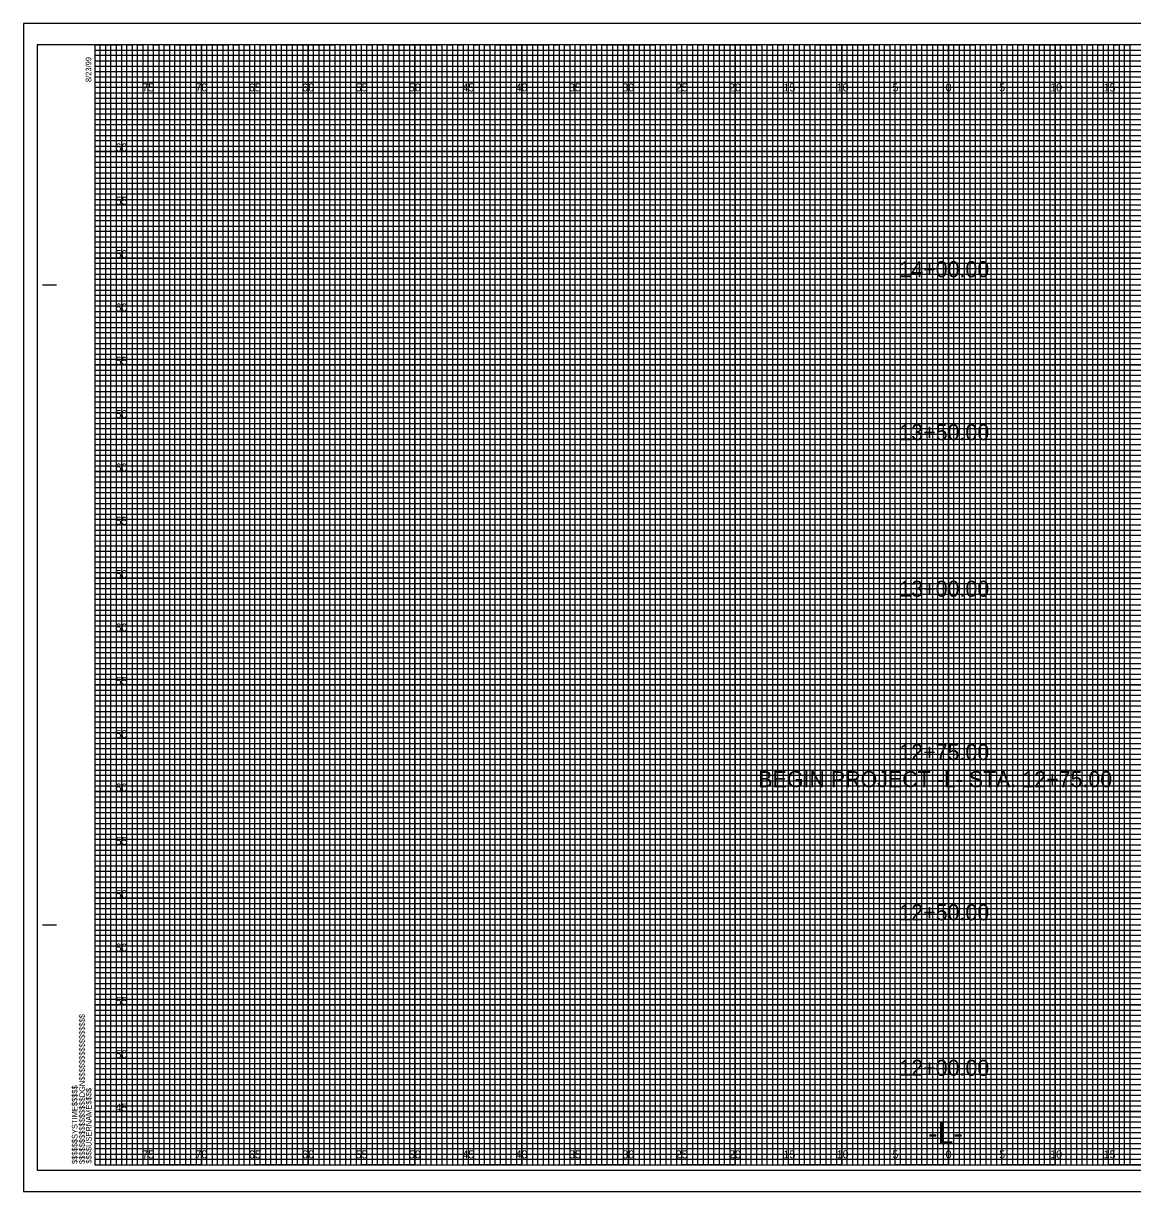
# Model space of a CAD drawing. Extents: x -7 to 193, y -2 to 107.
# Drawn here: x -6.7 to 97.2, y -2.5 to 107 of the extents above; entities that cross this region are included whole.
import ezdxf

# ---------------------------------------------------------------- set-up
doc = ezdxf.new("R2010")
doc.units = 0
for name, color, linetype in [('Exist XS Center Line Elevation Label', 7, 'Continuous'), ('Prop XS Alignment Label', 7, 'Continuous'), ('Prop XS Elevation Labels', 7, 'Continuous'), ('Prop XS Offset Labels', 7, 'Continuous'), ('Prop XS Station Labels', 7, 'Continuous'), ('Sheet Cross Section CELL', 7, 'Continuous'), ('Sheet Cross Section Grid Major CELL', 7, 'Continuous'), ('Sheet Cross Section Grid Middle CELL', 7, 'Continuous'), ('Sheet Cross Section Grid Minor 1 CELL', 7, 'Continuous'), ('Sheet Cross Section Grid Minor 2 CELL', 7, 'Continuous'), ('Sheet Cutting Line CELL', 7, 'Continuous'), ('Sheet DOT Grid CELL', 7, 'Continuous'), ('Sheet Plot Border Inside CELL', 7, 'Continuous'), ('Sheet Plot Border Outside CELL', 7, 'Continuous')]:
    doc.layers.add(name, color=color, linetype=linetype)

msp = doc.modelspace()

# ---------------------------------------------------------------- linework, layer by layer
at = {"layer": 'Sheet Cross Section CELL'}
for p, q in [((-4.9, 82.5), (-3.65, 82.5)), ((-4.85, 82.5), (-3.6, 82.5)), ((-4.9, 22.5), (-3.65, 22.5)), ((-4.85, 22.5), (-3.6, 22.5)), ((0, 0), (0, 0)), ((0, 0), (0, 0)), ((0, 0), (0, 0)), ((0, 0), (0, 0)), ((0, 0), (0, 0)), ((0, 0), (0, 0)), ((0, 0), (0, 0))]:
    msp.add_line(p, q, dxfattribs=at)
msp.add_lwpolyline([(160, 105), (0, 105), (0, 0), (160, 0)], close=True, dxfattribs=at)
at = {"layer": 'Sheet Cross Section Grid Major CELL'}
for p, q in [((5, 105), (0, 105)), ((5, 0), (5, 105)), ((15, 105), (10, 105)), ((10, 105), (10, 0)), ((15, 0), (15, 105)), ((25, 105), (20, 105)), ((20, 105), (20, 0)), ((25, 0), (25, 105)), ((35, 105), (30, 105)), ((30, 105), (30, 0)), ((35, 0), (35, 105)), ((45, 105), (40, 105)), ((40, 105), (40, 0)), ((45, 0), (45, 105)), ((55, 105), (50, 105)), ((50, 105), (50, 0)), ((55, 0), (55, 105)), ((65, 105), (60, 105)), ((60, 105), (60, 0)), ((65, 0), (65, 105)), ((75, 105), (70, 105)), ((70, 105), (70, 0)), ((75, 0), (75, 105)), ((85, 105), (80, 105)), ((80, 105), (80, 0)), ((85, 0), (85, 105)), ((95, 105), (90, 105)), ((90, 105), (90, 0)), ((95, 0), (95, 105)), ((10, 0), (5, 0)), ((20, 0), (15, 0)), ((30, 0), (25, 0)), ((40, 0), (35, 0)), ((50, 0), (45, 0)), ((60, 0), (55, 0)), ((70, 0), (65, 0)), ((80, 0), (75, 0)), ((90, 0), (85, 0)), ((100, 0), (95, 0))]:
    msp.add_line(p, q, dxfattribs=at)
for points in [[(0, 100), (160, 100), (160, 95), (0, 95)], [(0, 90), (160, 90), (160, 85), (0, 85)], [(0, 80), (160, 80), (160, 75), (0, 75)], [(0, 70), (160, 70), (160, 65), (0, 65)], [(0, 60), (160, 60), (160, 55), (0, 55)], [(0, 50), (160, 50), (160, 45), (0, 45)], [(0, 40), (160, 40), (160, 35), (0, 35)], [(0, 30), (160, 30), (160, 25), (0, 25)], [(0, 20), (160, 20), (160, 15), (0, 15)], [(0, 10), (160, 10), (160, 5), (0, 5)]]:
    msp.add_lwpolyline(points, dxfattribs=at)
at = {"layer": 'Sheet Cross Section Grid Middle CELL'}
for points in [[(0, 105), (2.5, 105), (2.5, 0), (7.5, 0), (7.5, 105), (12.5, 105), (12.5, 0), (17.5, 0), (17.5, 105), (22.5, 105), (22.5, 0), (27.5, 0), (27.5, 105), (32.5, 105), (32.5, 0), (37.5, 0), (37.5, 105), (42.5, 105), (42.5, 0), (47.5, 0), (47.5, 105), (52.5, 105), (52.5, 0), (57.5, 0), (57.5, 105), (62.5, 105), (62.5, 0), (67.5, 0), (67.5, 105), (72.5, 105), (72.5, 0), (77.5, 0), (77.5, 105), (82.5, 105), (82.5, 0), (87.5, 0), (87.5, 105), (92.5, 105), (92.5, 0), (97.5, 0)], [(0, 102.5), (137.5, 102.5)], [(135, 92.5), (160, 92.5), (160, 97.5), (0, 97.5)], [(0, 92.5), (130, 92.5)], [(0, 82.5), (160, 82.5), (160, 87.5), (0, 87.5)], [(0, 72.5), (160, 72.5), (160, 77.5), (0, 77.5)], [(0, 62.5), (160, 62.5), (160, 67.5), (0, 67.5)], [(0, 52.5), (160, 52.5), (160, 57.5), (0, 57.5)], [(0, 42.5), (160, 42.5), (160, 47.5), (0, 47.5)], [(0, 32.5), (160, 32.5), (160, 37.5), (0, 37.5)], [(0, 22.5), (160, 22.5), (160, 27.5), (0, 27.5)], [(0, 12.5), (160, 12.5), (160, 17.5), (0, 17.5)], [(0, 2.5), (160, 2.5), (160, 7.5), (0, 7.5)]]:
    msp.add_lwpolyline(points, dxfattribs=at)
at = {"layer": 'Sheet Cross Section Grid Minor 1 CELL'}
for p, q in [((0, 104.5), (130, 104.5)), ((130, 103.99), (0, 103.99)), ((0, 103.99), (0, 103.5)), ((0, 103.5), (130, 103.5)), ((130, 102.95), (0, 102.95)), ((0, 102.95), (0, 102)), ((0, 102), (160, 102))]:
    msp.add_line(p, q, dxfattribs=at)
for points in [[(0, 101.5), (135, 101.5), (160, 101.5), (160, 101), (0, 101)], [(0, 100.5), (160, 100.5), (160, 99.5), (0, 99.5)], [(0, 99), (160, 99), (160, 98.5), (0, 98.49)], [(0, 98), (160, 98), (160, 97), (0, 97)], [(0, 96.5), (160, 96.5), (160, 96), (0, 96)], [(0, 95.5), (160, 95.5), (160, 94.5), (135, 94.5)], [(130, 94.5), (0, 94.5)], [(0, 94), (130, 94)], [(130, 93.5), (0, 93.5)], [(0, 93), (130, 93)], [(130, 92), (0, 92)], [(0, 91.5), (160, 91.5), (160, 91), (0, 91)], [(0, 90.5), (160, 90.5), (160, 89.5), (0, 89.5)], [(0, 89), (160, 89), (160, 88.5), (0, 88.5)], [(0, 88), (160, 88), (160, 86.98), (160, 86.5), (160, 86), (0, 86)], [(0, 87), (160, 87), (160, 86.5), (0, 86.5)], [(0, 85.5), (160, 85.5), (160, 84.5), (0, 84.52)], [(0, 84.52), (160, 84.5), (160, 84), (0, 84)], [(0, 83.5), (160, 83.5), (160, 83), (0, 83)], [(0, 82), (160, 82), (160, 81.5), (0, 81.5)], [(0, 81), (160, 81), (160, 80.5), (0, 80.5)], [(-0.04, 79.45), (160, 79.45), (160, 78.94), (-0.04, 78.94)], [(0, 78.5), (160, 78.5), (160, 78), (0, 78)], [(0, 77), (160, 77), (160, 76.5), (0, 76.5)], [(0, 76), (160, 76), (160, 75.5), (0, 75.5)], [(0, 74.5), (160, 74.5), (160, 74), (0, 74)], [(0, 73.5), (160, 73.5), (160, 73), (0, 73)], [(0, 72), (160, 72), (160, 71.5), (0, 71.5)], [(0, 71), (160, 71), (160, 70.5), (0, 70.5)], [(0, 69.5), (160, 69.5), (160, 68.99), (0, 69)], [(0, 68.5), (160, 68.5), (160, 68), (0, 68)], [(0, 67), (160, 67), (160, 66.5), (0, 66.5)], [(0, 66), (160, 66), (160, 65.5), (0, 65.5)], [(0, 64.5), (160, 64.5), (160, 64), (0, 64)], [(0, 63.5), (160, 63.5), (160, 63), (0, 63)], [(0, 62), (160, 62), (160, 61.5), (0, 61.5)], [(0, 61), (160, 61), (160, 60.5), (0, 60.5)], [(0, 59.5), (160, 59.5), (160, 59), (0, 59)], [(0, 58.5), (160.03, 58.45), (160, 58), (0, 58)], [(0, 57), (160, 57), (160, 56.5), (0, 56.5)], [(0, 56), (160, 56), (160, 55.5), (0, 55.5)], [(0, 54.5), (160, 54.5), (160, 54), (0, 54)], [(0, 53.5), (160, 53.5), (160, 53), (0, 53)], [(0, 52), (160, 52), (160, 51.5), (0, 51.5)], [(0, 51), (160, 51), (160, 50.5), (0, 50.5)], [(0, 49.5), (160, 49.5), (160, 49), (0, 49)], [(0, 48.5), (160, 48.5), (160, 48), (0, 48)], [(0, 47), (160, 47), (160, 46.5), (0, 46.5)], [(0, 46), (160, 46), (160, 45.5), (0, 45.5)], [(0, 44.5), (160, 44.5), (160, 44), (0, 44)], [(0, 43.5), (160, 43.5), (160, 43), (0, 43)], [(0, 42), (160, 42), (160, 41.5), (0, 41.5)], [(0, 41), (160, 41), (160, 40.5), (0, 40.5)], [(0, 39.5), (160, 39.5), (160, 38.99), (0, 39)], [(0, 38.5), (160, 38.5), (160, 38), (0, 38)], [(0, 37), (160, 37), (160, 36.5), (0, 36.5)], [(0, 36), (160, 36), (160, 35.5), (0, 35.5)], [(0, 34.5), (160, 34.5), (160, 34), (0, 34)], [(0, 33.5), (160, 33.5), (160, 33), (0, 33)], [(0, 32), (160, 32), (160, 31.5), (0, 31.5)], [(0, 31), (160, 31), (160, 30.5), (0, 30.5)], [(0, 29.5), (160, 29.5), (160, 29), (0, 29)], [(0, 28.5), (160.03, 28.46), (160, 28), (0, 28)], [(0, 27), (160, 27), (160, 26.5), (0, 26.5)], [(0, 26), (160, 26), (160, 25.5), (0, 25.5)], [(0, 24.5), (160, 24.5), (160, 24), (0, 24)], [(0, 23.5), (160, 23.5), (160, 23), (0, 23)], [(0, 22), (160, 22), (160, 21.5), (0, 21.5)], [(0, 21), (160, 21), (160, 20.5), (0, 20.5)], [(0, 19.5), (160, 19.5), (160, 19), (0, 19)], [(0, 18.5), (160, 18.5), (160, 18), (0, 18)], [(0, 17), (160, 17), (160, 16.5), (0, 16.5)], [(0, 16), (160, 16), (160, 15.5), (0, 15.5)], [(0, 14.5), (160, 14.5), (160, 14), (0, 14)], [(0, 13.5), (160, 13.5), (160, 13), (0, 13)], [(0, 12), (160, 12), (160, 11.5), (0, 11.5)], [(0, 11), (160, 11), (160, 10.5), (0, 10.5)], [(0, 9.5), (160, 9.5), (160, 9), (0, 9)], [(0, 8.5), (160, 8.5), (160, 8), (0, 8)], [(0, 7), (160, 7), (160, 6.5), (0, 6.5)], [(0, 6), (160, 6), (160, 5.5), (0, 5.5)], [(0, 4.5), (160, 4.5), (160, 4), (0, 4)], [(0, 3.5), (160, 3.5), (160, 3), (0, 3)], [(0, 2), (160, 2), (160, 1.5), (0, 1.5)], [(0, 1), (160, 1), (160, 0.5), (0, 0.5)]]:
    msp.add_lwpolyline(points, dxfattribs=at)
at = {"layer": 'Sheet Cross Section Grid Minor 2 CELL'}
for points in [[(0, 0), (0.5, 0), (0.5, 105), (1, 105), (1, 0)], [(1, 0), (1.5, 0), (1.5, 105), (2, 105), (2, 0)], [(2.5, 0), (3, 0), (3, 105), (3.5, 105), (3.5, 0)], [(3.5, 0), (4, 0), (4, 105), (4.5, 105), (4.5, 0)], [(5, 0), (5.5, 0), (5.5, 105), (6, 105), (6, 0)], [(6, 0), (6.5, 0), (6.5, 105), (7, 105), (7, 0)], [(7.5, 0), (8, 0), (8, 105), (8.5, 105), (8.5, 0)], [(8.5, 0), (9, 0), (9, 105), (9.5, 105), (9.5, 0)], [(10, 0), (10.5, 0), (10.5, 105), (11, 105), (11, 0)], [(11, 0), (11.5, 0), (11.5, 105), (12, 105), (12, 0)], [(12.5, 0), (13, 0), (13, 105), (13.5, 105), (13.5, 0)], [(13.5, 0), (14, 0), (14, 105), (14.5, 105), (14.5, 0)], [(15, 0), (15.5, 0), (15.5, 105), (16, 105), (16, 0)], [(16, 0), (16.5, 0), (16.5, 105), (17, 105), (17, 0)], [(17.5, 0), (18, 0), (18, 105), (18.5, 105), (18.5, 0)], [(18.5, 0), (19, 0), (19, 105), (19.5, 105), (19.5, 0)], [(20, 0), (20.5, 0), (20.5, 105), (21, 105), (21, 0)], [(21, 0), (21.5, 0), (21.5, 105), (22, 105), (22, 0)], [(22.5, 0), (23, 0), (23, 105), (23.5, 105), (23.5, 0)], [(23.5, 0), (24, 0), (24, 105), (24.5, 105), (24.5, 0)], [(25, 0), (25.5, 0), (25.5, 105), (26, 105), (26, 0)], [(26, 0), (26.5, 0), (26.5, 105), (27, 105), (27, 0)], [(27.5, 0), (28, 0), (28, 105), (28.5, 105), (28.5, 0)], [(28.5, 0), (29, 0), (29, 105), (29.5, 105), (29.5, 0)], [(30, 0), (30.5, 0), (30.5, 105), (31, 105), (31, 0)], [(31, 0), (31.5, 0), (31.5, 105), (32, 105), (32, 0)], [(32.5, 0), (33, 0), (33, 105), (33.5, 105), (33.5, 0)], [(33.5, 0), (34, 0), (34, 105), (34.5, 105), (34.5, 0)], [(35, 0), (35.5, 0), (35.5, 105), (36, 105), (36, 0)], [(36, 0), (36.5, 0), (36.5, 105), (37, 105), (37, 0)], [(37.5, 0), (38, 0), (38, 105), (38.5, 105), (38.5, 0)], [(38.5, 0), (39, 0), (39, 105), (39.5, 105), (39.5, 0)], [(40, 0), (40.5, 0), (40.5, 105), (41, 105), (41, 0)], [(41, 0), (41.5, 0), (41.5, 105), (42, 105), (42, 0)], [(42.5, 0), (43, 0), (43, 105), (43.5, 105), (43.5, 0)], [(43.5, 0), (44, 0), (44, 105), (44.5, 105), (44.5, 0)], [(45, 0), (45.5, 0), (45.5, 105), (46, 105), (46, 0)], [(46, 0), (46.5, 0), (46.5, 105), (47, 105), (47, 0)], [(47.5, 0), (48, 0), (48, 105), (48.5, 105), (48.5, 0)], [(48.5, 0), (49, 0), (49, 105), (49.5, 105), (49.5, 0)], [(50, 0), (50.5, 0), (50.5, 105), (51, 105), (51, 0)], [(51, 0), (51.5, 0), (51.5, 105), (52, 105), (52, 0)], [(52.5, 0), (53, 0), (53, 105), (53.5, 105), (53.5, 0)], [(53.5, 0), (54, 0), (54, 105), (54.5, 105), (54.5, 0)], [(55, 0), (55.5, 0), (55.5, 105), (56, 105), (56, 0)], [(56, 0), (56.5, 0), (56.5, 105), (57, 105), (57, 0)], [(57.5, 0), (58, 0), (58, 105), (58.5, 105), (58.5, 0)], [(58.5, 0), (59, 0), (59, 105), (59.5, 105), (59.5, 0)], [(60, 0), (60.5, 0), (60.5, 105), (61, 105), (61, 0)], [(61, 0), (61.5, 0), (61.5, 105), (62, 105), (62, 0)], [(62.5, 0), (63, 0), (63, 105), (63.5, 105), (63.5, 0)], [(63.5, 0), (64, 0), (64, 105), (64.5, 105), (64.5, 0)], [(65, 0), (65.5, 0), (65.5, 105), (66, 105), (66, 0)], [(66, 0), (66.5, 0), (66.5, 105), (67, 105), (67, 0)], [(67.5, 0), (68, 0), (68, 105), (68.5, 105), (68.5, 0)], [(68.5, 0), (69, 0), (69, 105), (69.5, 105), (69.5, 0)], [(70, 0), (70.5, 0), (70.5, 105), (71, 105), (71, 0)], [(71, 0), (71.5, 0), (71.5, 105), (72, 105), (72, 0)], [(72.5, 0), (73, 0), (73, 105), (73.5, 105), (73.5, 0)], [(73.5, 0), (74, 0), (74, 105), (74.5, 105), (74.5, 0)], [(75, 0), (75.5, 0), (75.5, 105), (76, 105), (76, 0)], [(76, 0), (76.5, 0), (76.5, 105), (77, 105), (77, 0)], [(77.5, 0), (78, 0), (78, 105), (78.5, 105), (78.5, 0)], [(78.5, 0), (79, 0), (79, 105), (79.5, 105), (79.5, 0)], [(80, 0), (80.5, 0), (80.5, 105), (81, 105), (81, 0)], [(81, 0), (81.5, 0), (81.5, 105), (82, 105), (82, 0)], [(82.5, 0), (83, 0), (83, 105), (83.5, 105), (83.5, 0)], [(83.5, 0), (84, 0), (84, 105), (84.5, 105), (84.5, 0)], [(85, 0), (85.5, 0), (85.5, 105), (86, 105), (86, 0)], [(86, 0), (86.5, 0), (86.5, 105), (87, 105), (87, 0)], [(87.5, 0), (88, 0), (88, 105), (88.5, 105), (88.5, 0)], [(88.5, 0), (89, 0), (89, 105), (89.5, 105), (89.5, 0)], [(90, 0), (90.5, 0), (90.5, 105), (91, 105), (91, 0)], [(91, 0), (91.5, 0), (91.5, 105), (92, 105), (92, 0)], [(92.5, 0), (93, 0), (93, 105), (93.5, 105), (93.5, 0)], [(93.5, 0), (94, 0), (94, 105), (94.5, 105), (94.5, 0)], [(95, 0), (95.5, 0), (95.5, 105), (96, 105), (96, 0)], [(96, 0), (96.5, 0), (96.5, 105), (97, 105), (97, 0)]]:
    msp.add_lwpolyline(points, dxfattribs=at)
at = {"layer": 'Sheet Cutting Line CELL'}
for p, q in [((161.65, 107), (-6.7, 107)), ((-6.7, 107), (-6.7, -2.5)), ((-6.7, -2.5), (161.65, -2.5))]:
    msp.add_line(p, q, dxfattribs=at)
at = {"layer": 'Sheet DOT Grid CELL'}
for p, q in [((5, 0), (5, 105)), ((10, 0), (10, 105)), ((15, 0), (15, 105)), ((20, 0), (20, 105)), ((25, 0), (25, 105)), ((30, 0), (30, 105)), ((35, 0), (35, 105)), ((40, 0), (40, 105)), ((45, 0), (45, 105)), ((50, 0), (50, 105)), ((55, 0), (55, 105)), ((60, 0), (60, 105)), ((65, 0), (65, 105)), ((70, 0), (70, 105)), ((75, 0), (75, 105)), ((80, 0), (80, 105)), ((85, 0), (85, 105)), ((90, 0), (90, 105)), ((95, 0), (95, 105)), ((0, 100), (160, 100)), ((0, 95), (160, 95)), ((0, 90), (160, 90)), ((0, 85), (160, 85)), ((0, 80), (160, 80)), ((0, 75), (160, 75)), ((0, 70), (160, 70)), ((0, 65), (160, 65)), ((0, 60), (160, 60)), ((0, 55), (160, 55)), ((0, 50), (160, 50)), ((0, 45), (160, 45)), ((0, 40), (160, 40)), ((0, 35), (160, 35)), ((0, 30), (160, 30)), ((0, 25), (160, 25)), ((0, 20), (160, 20)), ((0, 15), (160, 15)), ((0, 10), (160, 10)), ((0, 5), (160, 5))]:
    msp.add_line(p, q, dxfattribs=at)
at = {"layer": 'Sheet Plot Border Inside CELL'}
msp.add_lwpolyline([(-5.4, -0.5), (161.2, -0.5), (161.2, 105), (-5.4, 105)], close=True, dxfattribs=at)
at = {"layer": 'Sheet Plot Border Outside CELL'}
msp.add_lwpolyline([(-6.7, -2.5), (161.65, -2.5), (161.65, 107), (-6.7, 107)], close=True, dxfattribs=at)

# ---------------------------------------------------------------- texts
at = {"layer": 'Exist XS Center Line Elevation Label'}
msp.add_text('BEGIN PROJECT -L- STA. 12+75.00', height=1.5, dxfattribs=at).set_placement((62.17, 35.41))
at = {"layer": 'Prop XS Alignment Label'}
msp.add_text('-L-', height=2, dxfattribs=at).set_placement((78.08, 2))
at = {"layer": 'Prop XS Elevation Labels'}
for s, p in [('60', (1.93, 95)), ('55', (1.94, 90)), ('50', (1.93, 85)), ('60', (1.93, 80)), ('55', (1.94, 75)), ('50', (1.93, 70)), ('60', (1.93, 65)), ('55', (1.94, 60)), ('50', (1.93, 55)), ('60', (1.93, 50)), ('55', (1.94, 45)), ('50', (1.93, 40)), ('60', (1.93, 35)), ('55', (1.94, 30)), ('50', (1.93, 25)), ('60', (1.93, 20)), ('55', (1.94, 15)), ('50', (1.93, 10)), ('45', (1.94, 5))]:
    msp.add_text(s, height=0.75, dxfattribs=at).set_placement(p)
at = {"layer": 'Prop XS Offset Labels'}
for s, p in [('75', (4.44, 100.62)), ('70', (9.43, 100.62)), ('65', (14.44, 100.62)), ('60', (19.43, 100.62)), ('55', (24.44, 100.62)), ('50', (29.43, 100.62)), ('45', (34.44, 100.62)), ('40', (39.43, 100.62)), ('35', (44.44, 100.62)), ('30', (49.43, 100.62)), ('25', (54.44, 100.62)), ('20', (59.43, 100.62)), ('15', (64.53, 100.62)), ('10', (69.52, 100.62)), ('5', (74.74, 100.62)), ('0', (79.73, 100.62)), ('0', (79.73, 100.62)), ('5', (84.74, 100.62)), ('10', (89.52, 100.62)), ('15', (94.53, 100.62)), ('75', (4.44, 0.62)), ('70', (9.43, 0.62)), ('65', (14.44, 0.62)), ('60', (19.43, 0.62)), ('55', (24.44, 0.62)), ('50', (29.43, 0.62)), ('45', (34.44, 0.62)), ('40', (39.43, 0.62)), ('35', (44.44, 0.62)), ('30', (49.43, 0.62)), ('25', (54.44, 0.62)), ('20', (59.43, 0.62)), ('15', (64.53, 0.62)), ('10', (69.52, 0.62)), ('5', (74.74, 0.62)), ('0', (79.73, 0.62)), ('0', (79.73, 0.62)), ('5', (84.74, 0.62)), ('10', (89.52, 0.62)), ('15', (94.53, 0.62))]:
    msp.add_text(s, height=0.75, dxfattribs=at).set_placement(p)
at = {"layer": 'Prop XS Station Labels'}
for s, p in [('14+00.00', (75.39, 83.21)), ('13+50.00', (75.39, 67.93)), ('13+00.00', (75.39, 53.26)), ('12+75.00', (75.39, 37.95)), ('12+50.00', (75.39, 22.93)), ('12+00.00', (75.39, 8.36))]:
    msp.add_text(s, height=1.5, dxfattribs=at).set_placement(p)
at = {"layer": 'Sheet Cross Section CELL'}
for s, p in [('8/23/99', (-0.33, 101.5)), ('$$$$$$$$$$$$$$$$DGN$$$$$$$$$$$$$$$$', (-0.94, 0.09)), ('$$$$$$SYSTIME$$$$$', (-1.63, 0.09)), ('$$$$USERNAME$$$$', (-0.31, 0.12))]:
    msp.add_text(s, height=0.525, rotation=90, dxfattribs=at).set_placement(p)

doc.saveas('drawing.dxf')
